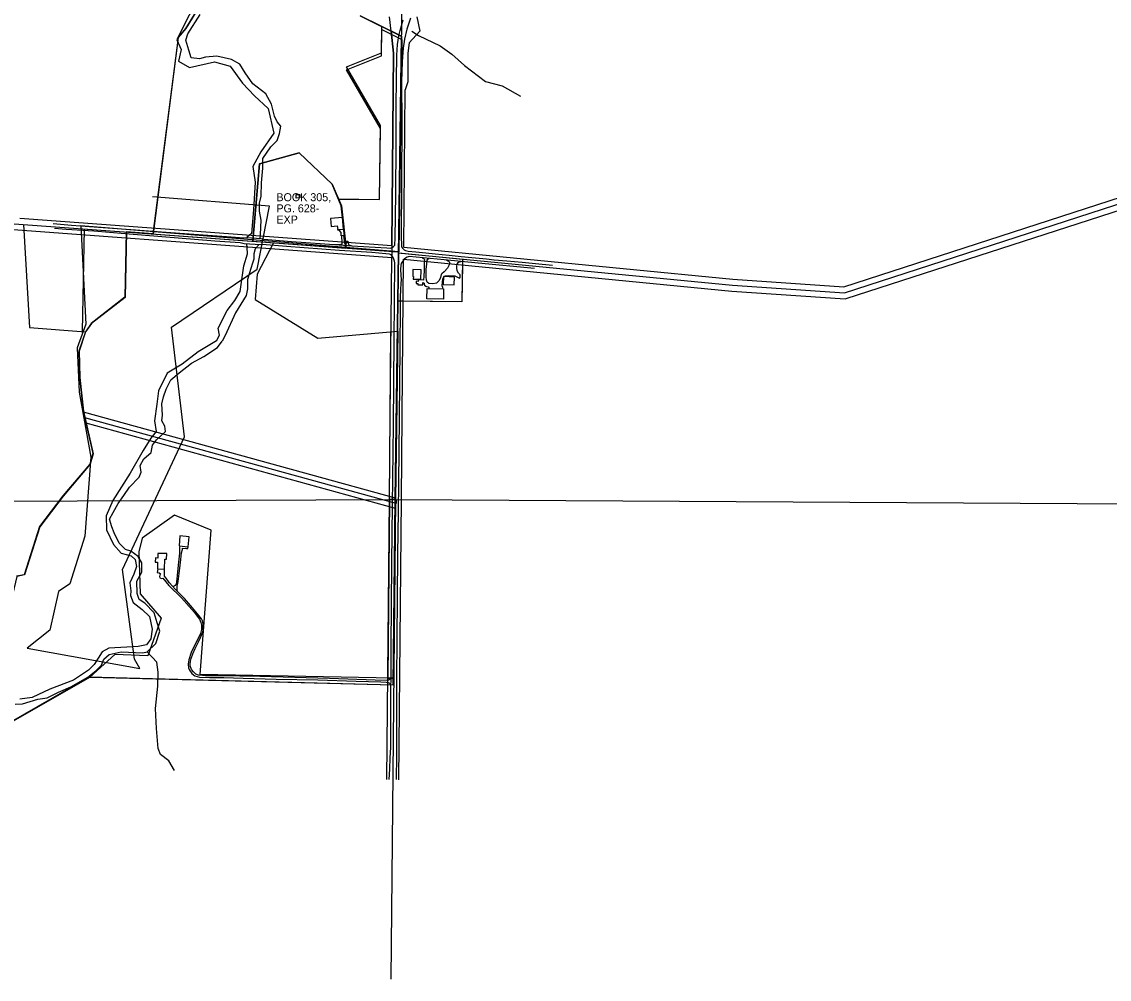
# Model space of a CAD drawing. Extents: x 171944 to 348094, y 278777 to 304794.
# Drawn here: x 175290 to 180723, y 283855 to 288639 of the extents above; entities that cross this region are included whole.
import ezdxf

# ---------------------------------------------------------------- set-up
doc = ezdxf.new("R2010")
doc.units = 0
for name, color, linetype in [('_CIVIL_CONSTRUCTION', 7, 'Continuous'), ('Default', 7, 'Continuous'), ('DR_Ditch', 7, 'Continuous'), ('DR_P_Erosion_Control', 7, 'Continuous'), ('DR_X_Ditch', 7, 'Continuous'), ('PF_P_Text_Strip_Grades_50', 7, 'Continuous'), ('PF_X_Text_Strip_Grade', 7, 'Continuous'), ('PV_P_Curb', 7, 'Continuous'), ('PV_X_Driveway', 7, 'Continuous'), ('RW_P_Const_Limits', 7, 'Continuous'), ('SH_Border', 7, 'Continuous'), ('SV_X_Toe_of_Slope', 7, 'Continuous'), ('UT_X_Electric', 7, 'Continuous')]:
    doc.layers.add(name, color=color, linetype=linetype)

msp = doc.modelspace()

# ---------------------------------------------------------------- linework, layer by layer
at = {"layer": '_CIVIL_CONSTRUCTION'}
for p, q in [((177135, 288591.8), (177127, 288663.2)), ((177264.1, 288662.8), (177278.5, 288592.3)), ((177147.2, 288481.8), (177135, 288591.8)), ((177278.5, 288592.3), (177225.9, 288533)), ((177225.9, 288533), (177219.3, 288481.1)), ((177138.6, 287521.5), (177147.2, 288481.8)), ((177219.3, 288481.1), (177218, 288338.6)), ((177218, 288338.6), (177205.6, 288298.7)), ((177198.5, 287512.3), (177205.6, 288298.7)), ((179396.6, 287314.9), (181543, 288010.2)), ((179409.6, 287256), (181561.3, 287953.1)), ((175280.8, 287657.8), (177138.6, 287521.5)), ((175224.4, 287601.8), (176532.3, 287505.8)), ((176532.3, 287505.8), (177138.1, 287461.4)), ((177130.9, 286673.3), (177138.1, 287461.4)), ((177190.9, 286672.8), (177198, 287452.1)), ((179404.1, 287254.3), (179409.6, 287256)), ((177127.1, 286252.6), (177130.9, 286673.3)), ((177187.1, 286252), (177190.9, 286672.8)), ((177113.3, 284852.7), (177127.1, 286252.6)), ((177173.3, 284852.1), (177187.1, 286252))]:
    msp.add_line(p, q, dxfattribs=at)
for points in [[(177198.5, 287512.3), (178843, 287352.1), (179396.6, 287314.9)], [(177198, 287452.1), (178838.1, 287292.3), (179404.1, 287254.3)]]:
    msp.add_lwpolyline(points, dxfattribs=at)
at = {"layer": 'Default'}
msp.add_line((177138.6, 287521.5), (177138.1, 287461.4), dxfattribs=at)
for points in [[(177138.6, 287521.5), (177138.3, 287491.5), (177173.8, 287488.9), (177188.3, 288565.8), (177134.9, 288592), (177147.2, 288481.8)], [(177127.1, 286252.2), (177134.7, 287089.8), (177168.4, 287092.8), (177157.1, 286252.3)], [(177118.3, 285360.2), (177148.3, 285359.7), (177157.1, 286252.3), (177127.1, 286252.2)]]:
    msp.add_lwpolyline(points, close=True, dxfattribs=at)
at = {"layer": 'DR_Ditch'}
for points in [[(176190.2, 288795.8), (176094.6, 288610.5), (176064.4, 288548.9), (176086.7, 288500.3), (176072.5, 288441.9)], [(176480.8, 287555.4), (176481.9, 287576.3), (176485.6, 287647.4), (176478.2, 287692.3), (176477.1, 287732.1), (176486.6, 287766.8), (176487.7, 287833.4), (176493.6, 287907.2), (176493.5, 287955.6), (176535, 288014.3), (176566, 288045.7), (176578.1, 288080.4), (176583.9, 288116.5), (176565.3, 288139.1), (176552.2, 288167.8), (176538, 288226.3), (176508.6, 288279.4), (176444.3, 288327.8), (176405.3, 288383.3), (176380, 288427), (176338.1, 288450), (176264.4, 288466.5), (176208.4, 288462.4), (176178.3, 288453.4), (176136.4, 288458.1), (176125.2, 288496.5), (176109.9, 288546.6), (176119.3, 288579.1), (176180.6, 288674.7)], [(176072.5, 288441.9), (176127.6, 288410.8), (176252.8, 288438.4), (176330.6, 288417.1), (176392.5, 288332.1), (176452.1, 288268.4), (176521.7, 288205.2), (176550, 288081.3), (176484.5, 287989.2), (176445, 287914.8), (176456.8, 287836.9), (176447.4, 287698.8), (176438.1, 287581.2), (176413.6, 287561)], [(176263.1, 287045.4), (176277.9, 287072.6), (176271.4, 287107.4), (176316.8, 287195.9), (176355.2, 287246.1), (176380.5, 287291), (176389.9, 287349.4), (176398.8, 287419), (176417.7, 287479.2), (176415.6, 287510.3), (176415.2, 287529)], [(176473.8, 287524.8), (176455.9, 287503.6), (176449.5, 287479.3), (176450.1, 287452.7), (176443, 287432), (176433.6, 287406.1), (176417.1, 287351.8), (176417.1, 287303.9), (176411.2, 287270.9), (176357.5, 287184.1), (176306.8, 287070.8), (176291.5, 287043.6)], [(175257.2, 285229.3), (175293.2, 285231.1), (175369.3, 285254.1), (175417.1, 285261.8), (175473.1, 285290.1), (175534.4, 285316.6), (175619.4, 285363.8), (175659.4, 285396.7), (175688.3, 285425), (175700.1, 285454), (175726.6, 285478.2), (175786.2, 285490.6), (175894.7, 285485.2), (175916.5, 285491.2), (175959, 285533.1), (175980.2, 285593.9), (175966.1, 285635.2), (175951.9, 285686.5), (175905.3, 285734.3), (175876.4, 285752), (175867, 285781.6), (175865.2, 285843.5), (175889.4, 285889.6), (175890, 285936.2), (175871.7, 285966.9), (175834.5, 285993.5), (175807.5, 286002.3), (175776.1, 286034), (175752.2, 286085.6), (175740.1, 286115.6), (175728.6, 286153.8), (175746.5, 286187.8), (175771.8, 286232.4), (175799.4, 286272.8), (175828.4, 286314.3), (175875.6, 286363.2), (175886.7, 286388.5), (175880.6, 286421.6), (175900.5, 286455), (175936.9, 286487), (175942.6, 286523.1), (175962.5, 286549.4), (175990.2, 286575.4), (176008.4, 286591.6), (176005.3, 286618.9), (175989.2, 286644.5), (175992.5, 286673.9), (175989.5, 286730.2), (175998.6, 286764.3), (176012.1, 286802.7), (176034, 286849.6), (176075.8, 286884), (176137.7, 286932.9), (176199.1, 286966.6), (176268.1, 287011.4), (176291.5, 287043.6)], [(176263.1, 287045.4), (176170.5, 286989.3), (176092.1, 286927.3), (176016.7, 286882.9), (175972.4, 286795.1), (175964.1, 286727.9), (175953.8, 286645.3), (175962, 286591.6), (175935.2, 286558.5), (175896, 286496.5), (175830.7, 286384.2), (175745, 286247.8), (175711, 286170.4), (175714, 286101.2), (175748.1, 286027.8), (175787.3, 285983.4), (175836.9, 285970), (175856.2, 285953.1), (175862.3, 285917), (175850.5, 285878.6), (175829.8, 285835.5), (175834.6, 285796), (175833.4, 285772.4), (175846.4, 285737), (175891.8, 285702.1), (175927.8, 285667.9), (175941.9, 285604.8), (175934.8, 285555.8), (175912.4, 285525.7), (175871.7, 285517.4), (175814.5, 285515), (175784.4, 285512.7), (175724.9, 285509.7), (175691.2, 285491.4), (175652.3, 285428.3), (175624, 285399.5), (175547.6, 285349.9), (175429.9, 285304.5), (175341.2, 285263.1), (175280.3, 285254.9)]]:
    msp.add_lwpolyline(points, dxfattribs=at)
at = {"layer": 'DR_P_Erosion_Control'}
for p, q in [((177157.2, 286259.3), (175598.5, 286688.6)), ((177156.7, 286207.6), (175611.9, 286633.1))]:
    msp.add_line(p, q, dxfattribs=at)
at = {"layer": 'DR_X_Ditch'}
for points in [[(177238.7, 288592), (177272.3, 288570.3), (177380.1, 288518.9), (177438.3, 288476.1), (177501.5, 288420.8), (177606.9, 288339.5), (177690.4, 288318.4), (177781.3, 288267.2)], [(176052.9, 284898.2), (176024, 284947), (175982.5, 284977.7), (175971.6, 285008.5), (175962.6, 285107.9), (175957.2, 285207.3), (175969.8, 285319.4), (175971.6, 285389.9), (175965.3, 285438.6), (175916.5, 285491.2)]]:
    msp.add_lwpolyline(points, dxfattribs=at)
at = {"layer": 'PF_P_Text_Strip_Grades_50'}
for points in [[(176209.2, 288769.2), (176108.8, 288605.8), (176072, 288560.6), (175946.6, 287579), (175812.1, 287588.9), (175805.2, 287262), (175636.7, 287132.1), (175607.7, 287090.1), (175575.6, 286993.2), (175578.4, 286862.5), (175596.4, 286693.9), (175645.4, 286481), (175630.7, 286428.9), (175494.7, 286269.7), (175378.5, 286116.7), (175302.3, 285875.9), (175263.9, 285868.2)], [(177155.3, 286252.2), (177187.8, 288566.1), (176980.6, 288668)], [(177173.8, 287488.9), (176910.4, 287508.2), (176886.6, 287719.5), (176872.2, 287753.2), (177077.3, 287750), (177082.1, 288105.3), (176912, 288398.5), (177087.1, 288467.8), (177088.9, 288599.7), (177188.2, 288550.4), (177173.8, 287488.9)], [(177155.3, 286252.2), (177172.7, 287488.4), (176909.3, 287507.9), (176885.6, 287719.1), (176840, 287826.6), (176675.3, 287984.3), (176477.5, 287929.4), (176443.6, 287542.3), (176909.3, 287507.9)], [(177173.8, 287488.9), (175585.2, 287618.5), (175610.2, 287128.1), (175567.2, 287008.9), (175575.8, 286788.7), (175635, 286464), (175605.1, 286069.2), (175529.7, 285829.9), (175473.6, 285791.6), (175429.7, 285599.9), (175316.9, 285509.5), (175880.1, 285408.4), (175853.3, 285453.9), (175828.7, 285641), (175793.1, 285902.6), (176102.1, 286565.4), (176037.4, 287112.7), (176466.3, 287402), (176527.5, 287716.9), (175943.4, 287764.5)], [(177173.8, 287488.9), (175585.2, 287618.5), (175610.2, 287128.1), (175567.2, 287008.9), (175575.8, 286788.7), (175635, 286464), (175605.1, 286069.2), (175529.7, 285829.9), (175473.6, 285791.6), (175429.7, 285599.9), (175316.9, 285509.5), (175880.1, 285408.4), (175853.3, 285453.9), (175828.7, 285641), (175793.1, 285902.6), (176102.1, 286565.4), (176037.4, 287112.7), (176466.3, 287402), (176527.5, 287716.9), (175943.4, 287764.5)], [(177157.1, 286252.3), (177170.5, 287243.6), (177173.7, 287485.1), (177491.6, 287453), (177491.3, 287424.1), (177488.8, 287239.3), (177196.7, 287243.3), (177170.5, 287243.6)], [(177159.8, 286251.6), (177159.7, 286232.7), (175605.5, 286660.8), (175598, 286693.2), (175580.1, 286861.3)], [(175115.7, 285073.7), (175626.9, 285365.7), (177145.7, 285325.6), (177155.3, 286252.2)]]:
    msp.add_lwpolyline(points, dxfattribs=at)
at = {"layer": 'PF_X_Text_Strip_Grade'}
for p, q in [((176980.6, 288668), (177188.3, 288565.8)), ((175600.8, 287604.3), (175591.1, 287090.9))]:
    msp.add_line(p, q, dxfattribs=at)
for points in [[(175947, 287578.6), (176072.4, 288560.2), (176109.2, 288605.4), (176209.6, 288768.8), (176200, 288859.9), (176254.9, 289020.7), (176333, 289127.4), (176498.7, 289254.3), (176610.8, 289298), (176648, 289429.6), (176701.7, 289556.9), (176779.7, 289767.2), (176722, 289836.7), (176723.8, 289912.1), (176737.4, 289958.6), (176723.2, 290042.2), (176664.9, 290144.8), (176734.7, 290227.2), (176779.1, 290304.8), (176742.5, 290399.8), (176794, 290571.3), (176771.6, 290709.4), (176767.2, 290821.3)], [(176443.6, 287542.3), (176477.5, 287929.4), (176675.3, 287984.3), (176840, 287826.6), (176886.6, 287719.5), (176910.4, 287508.2)], [(175298.7, 287626.4), (175328.5, 287111.2), (175609.1, 287089.5)], [(175812.7, 287588.7), (175806.6, 287261.4), (175638.1, 287131.5), (175609.1, 287089.5), (175577.1, 286992.6), (175579.9, 286861.9), (175598, 286693.2), (175647.1, 286480.4), (175632.4, 286428.2), (175496.4, 286269), (175380.4, 286115.9), (175304.3, 285875.1), (175265.9, 285867.4), (175221.5, 285684.8), (174927.1, 285439.6), (174550.6, 284781), (175118.1, 285072.9), (175629.1, 285365.1), (177148, 285325.7)], [(176547.2, 287534.8), (176466.4, 287378), (176455.9, 287250.8), (176769.9, 287057.5), (177168.4, 287092.8)], [(177491.6, 287453.6), (177488.8, 287239.1), (177170.5, 287243.4)], [(177148.3, 285359.7), (176180.9, 285377.7), (176236.4, 286099.1), (176053.1, 286174.4), (175891.7, 286058.5), (175874.6, 285990.9), (175880.7, 285781), (175986.7, 285659.8), (175920.5, 285471.5), (175755.3, 285477.3), (175629.1, 285365.1)]]:
    msp.add_lwpolyline(points, dxfattribs=at)
at = {"layer": 'PV_P_Curb'}
for p, q in [((177087.2, 288483.1), (177089, 288614.7)), ((176912.1, 288413.8), (177087.2, 288483.1)), ((177082.3, 288120.5), (176912.1, 288413.8)), ((177077.3, 287750), (177082.3, 288120.5)), ((176871.9, 287753.3), (177077.3, 287750))]:
    msp.add_line(p, q, dxfattribs=at)
msp.add_lwpolyline([(176871.9, 287753.3), (177077.3, 287750), (177082.3, 288120.5)], dxfattribs=at)
at = {"layer": 'PV_X_Driveway'}
for points in [[(176854.2, 287525.9), (176867.7, 287526.3), (176884, 287526.8), (176888.3, 287526.6), (176890.1, 287528.6), (176891.1, 287534.7), (176890.6, 287545.1), (176889.6, 287558), (176888.8, 287570), (176886, 287570), (176885.4, 287585.3), (176875.8, 287598.2), (176869.3, 287597.2), (176868.4, 287600.1)], [(176897.9, 287603.2), (176900.9, 287570.5), (176888.8, 287570)], [(176897.8, 287570.4), (176900.4, 287545.5), (176901, 287537.5), (176902.8, 287531.9), (176906.2, 287526.7), (176909.3, 287523), (176911.3, 287525.9), (176912.8, 287533.2), (176912.5, 287543.1), (176919.3, 287542.8), (176920.7, 287539.6), (176920.1, 287533.2), (176922.2, 287527.5), (176924.6, 287524.1), (176938.8, 287520.1)], [(177290.6, 287459.1), (177297, 287455.8), (177301.8, 287450.2), (177300.6, 287436.9), (177300.4, 287395.6), (177299.1, 287367.7), (177297.4, 287348.5), (177270.4, 287349.2), (177270.1, 287341.2), (177261.1, 287342.1), (177260.6, 287331.8), (177269.4, 287331.8), (177269.1, 287324.2), (177293.6, 287324.2), (177294.2, 287331.1), (177294.3, 287335.4), (177297.8, 287334.6), (177299.8, 287332.8), (177300.7, 287328.1), (177302.9, 287323.5), (177308.9, 287318.2), (177312.7, 287316.5), (177319.7, 287314.3), (177323.7, 287313.3), (177323.5, 287305.9)], [(177412.7, 287447.9), (177421.4, 287443.4), (177426.8, 287436.9), (177425.8, 287424.7), (177417.3, 287407.6), (177399.6, 287390.1), (177388.8, 287380), (177385, 287376), (177381.9, 287361.5), (177374.8, 287345.7), (177361.3, 287333), (177343.4, 287328.6), (177324.3, 287330.7), (177315.5, 287338), (177312, 287348.2), (177310.1, 287364.8), (177311.2, 287402), (177314.1, 287427.4), (177316, 287446.9), (177319.5, 287452.1), (177324.7, 287456)], [(177435.1, 287369.5), (177453.8, 287368.7), (177466.3, 287363.5), (177476.7, 287357.9), (177480.1, 287361.8), (177479.6, 287374.7), (177472.6, 287383.3), (177465.7, 287393.6), (177463.6, 287409), (177463.2, 287418), (177464.7, 287428.1), (177470.5, 287436.5), (177474.6, 287439.6), (177485.9, 287440.8)], [(177394.9, 287303.9), (177394.4, 287310.6), (177391, 287319.3), (177392.5, 287339.6), (177394.1, 287353.5), (177397, 287361.9)], [(177400.6, 287366.2), (177405.4, 287369.7), (177422, 287371.4), (177435.1, 287369.5), (177453.8, 287368.7)], [(176080.1, 286020.1), (176078.5, 286010.3), (176077.6, 285984.5), (176073.1, 285938.2), (176067, 285873.6), (176065.4, 285854), (176061.1, 285829.6), (176055.9, 285822.4), (176046.1, 285816.3)], [(176067.7, 285793.1), (176065.9, 285801.7), (176066.8, 285819), (176069.6, 285832.3), (176073.7, 285855.7), (176079.7, 285909.7), (176085.1, 285951.7), (176088.4, 285986), (176092.4, 286001.6), (176093.7, 286008.8), (176113.6, 286006.8), (176120.1, 286006.6), (176121.8, 286016.3)], [(175968.9, 285905.1), (175967, 285887.2), (175976.6, 285886), (175982.5, 285880), (175980.1, 285874.8), (175978.3, 285867), (175980.1, 285860.4), (175987.8, 285857.4), (175994.7, 285858.8), (176025.1, 285823.2), (176087.3, 285760.4), (176126, 285717.2), (176152.8, 285687.9), (176166.7, 285669.8), (176177.4, 285653.8), (176184.6, 285637.8), (176188.6, 285623.5), (176187.7, 285602.3), (176182.5, 285583.1), (176172.6, 285561.3), (176154.9, 285526.4), (176136.6, 285487.7), (176125.3, 285451), (176121.4, 285429.7), (176122.4, 285411.5), (176127.8, 285399.8), (176139.1, 285382.4), (176154.7, 285371.8), (176178.4, 285364.3), (176228.1, 285363), (176298.8, 285362.4), (176395.7, 285360.1), (176561.1, 285354.7), (176768.9, 285350.4), (176961.5, 285344.5), (177083.2, 285340.4), (177110.6, 285339.5), (177120.3, 285337.2), (177130, 285332.1), (177134.4, 285324)], [(177134.8, 285359.4), (177130, 285354.4), (177122.4, 285349.4), (177113.5, 285348.2), (177055.5, 285349.8), (176827.7, 285357.1), (176479.2, 285367.1), (176277.5, 285371.3), (176208.4, 285371.4), (176192.6, 285372.5), (176172.6, 285375.2), (176159.9, 285380.1), (176147.4, 285390.8), (176138.3, 285402.1), (176131.8, 285421.3), (176132, 285429.9), (176133.5, 285444.3), (176136.6, 285457.6), (176144.7, 285481.1), (176155.9, 285508.3), (176172.4, 285541.5), (176182.9, 285562.3), (176192.2, 285585.3), (176195.4, 285596.9), (176196.4, 285608.1), (176197, 285616.7), (176196.2, 285628.5), (176192.1, 285645.3), (176187.1, 285656.3), (176168.4, 285681.5), (176143.6, 285711.6), (176102.5, 285756.8), (176058.5, 285802.4), (176027.1, 285838.1), (176010.5, 285858.7), (176003.6, 285869.5), (176003.6, 285874.1), (176002.9, 285903.6)]]:
    msp.add_lwpolyline(points, dxfattribs=at)
at = {"layer": 'RW_P_Const_Limits'}
for p, q in [((177157.1, 286252.3), (177192.7, 288892.2)), ((174537, 286240.3), (177157.1, 286252.3)), ((177157.1, 286252.3), (182447, 286220.4))]:
    msp.add_line(p, q, dxfattribs=at)
at = {"layer": 'SH_Border'}
for p, q in [((175252.6, 287629.8), (177173.8, 287488.9)), ((175252.6, 287629.8), (177168.3, 287489.3)), ((177157.1, 286252.3), (177133.4, 283855.3))]:
    msp.add_line(p, q, dxfattribs=at)
for points in [[(179400.4, 287284.6), (181552.2, 287981.7), (182472.1, 288269.2)], [(177168.3, 287485.1), (178840.6, 287322.2), (179400.4, 287284.6)]]:
    msp.add_lwpolyline(points, dxfattribs=at)
at = {"layer": 'SV_X_Toe_of_Slope'}
for points in [[(176679.8, 287758.6), (176661, 287757.6), (176660.3, 287775), (176679.6, 287776), (176679.8, 287759.3)], [(176868.4, 287600.1), (176897.9, 287603.2), (176891.9, 287661), (176832.4, 287655.2), (176836.1, 287615.7), (176866.5, 287619.2)], [(177243, 287366.6), (177246.6, 287366.4), (177246.2, 287353.5), (177284.6, 287352.2), (177286.1, 287399.8), (177244.1, 287401.1)], [(177396.2, 287326), (177450.8, 287324.3), (177452.4, 287363.1), (177397.8, 287365.8)], [(177315.3, 287306), (177397.8, 287303.7), (177396.7, 287253.5), (177314.1, 287254.1)], [(176075.7, 286020.3), (176121.8, 286016.3), (176125.9, 286065.9), (176080.4, 286070.2)], [(175967.5, 285905.7), (176002.9, 285903.6), (176005.2, 285953.2), (176013.3, 285953.2), (176014, 285982.2), (175970.2, 285982.9), (175969.2, 285959.6), (175957.4, 285960.3), (175957, 285938.7), (175968.5, 285938.7)]]:
    msp.add_lwpolyline(points, close=True, dxfattribs=at)
at = {"layer": 'UT_X_Electric'}
for points in [[(175446.9, 287630.2), (175537.8, 287622.4), (175673.2, 287613.1), (175858.3, 287599.6), (175988.5, 287589.8), (176150.3, 287576.9), (176335.7, 287564.8), (176398.9, 287560), (176413.6, 287561), (176486.7, 287555.2), (176498.5, 287551.9), (176637.2, 287540.4), (176876, 287524.3), (176938.8, 287520.1), (177114.4, 287508.5), (177130.4, 287507.9), (177140.6, 287511.3), (177147, 287515.7), (177153.1, 287522.8), (177154.3, 287527.4), (177155, 287553.6), (177157.4, 287669), (177158.4, 287776.6), (177160.5, 288025.1), (177160.9, 288216.9), (177162.5, 288349.7), (177163.8, 288471), (177167.5, 288525.3), (177174.2, 288569.1), (177179.9, 288595.3), (177195.7, 288647.5)], [(177232.6, 288656.2), (177213.1, 288602.2), (177202.7, 288552.1), (177195.6, 288506), (177190.1, 288439.5), (177187.2, 288337.8), (177188.7, 288132.3), (177185.2, 287558.4), (177186.5, 287528.5), (177187.9, 287514.2), (177192.4, 287507.8), (177200, 287498.8), (177207.5, 287495.9), (177220.1, 287493.4), (177259.5, 287489), (177309.3, 287483.7), (177354.6, 287478.9), (177424.7, 287472.3), (177486.1, 287466.6), (177538.2, 287461.6), (177612.7, 287453.9), (177650.1, 287450.1), (177713.1, 287444.6), (177789.7, 287437), (177856.3, 287430.5), (177941, 287422.6)], [(177126, 284852.9), (177128.5, 284905.1), (177130.5, 284962.1), (177134.1, 285013.6), (177134.4, 285075.3), (177134.3, 285160), (177134.3, 285305.4), (177135.1, 285366.7), (177135.7, 285514.9), (177138.9, 285936.4), (177143, 286223.6), (177146.9, 286623.1), (177151.3, 287047.5), (177153.7, 287433.7), (177152.9, 287442.2), (177147.3, 287457.2), (177142.5, 287465.5), (177134.8, 287474), (177126.5, 287477.2), (177109.6, 287479.3), (177039, 287485.3), (176877.2, 287496.6), (176613.4, 287516.1), (176490.4, 287525.9), (176481.9, 287524), (176401.2, 287530), (176381.2, 287533.7), (176253.8, 287542.9), (175806.8, 287578.9), (175649.8, 287592.4), (175511.6, 287601.4), (175454, 287605.1)], [(177852.4, 287405.8), (177571, 287432.8), (177399.8, 287449.3), (177226.3, 287465.2), (177215, 287462.8), (177202.3, 287454.8), (177191.5, 287441.6), (177186.3, 287431.3), (177183.9, 287422), (177183, 287401.5), (177183.9, 287372.8), (177185.3, 287351.2), (177184.4, 287329.7), (177182.7, 287302.5), (177180.6, 287261), (177180.4, 287208.4), (177179, 287012.2), (177175.1, 286657.4), (177172.3, 286335.4), (177170.3, 286192.9), (177168, 285977.6), (177165.5, 285762.5), (177161.8, 285350), (177161.9, 285305.3), (177161.4, 285264.5), (177161.5, 285169.3), (177161.8, 284973.1), (177160.6, 284852.9)]]:
    msp.add_lwpolyline(points, dxfattribs=at)

# ---------------------------------------------------------------- texts
at = {"layer": 'PF_P_Text_Strip_Grades_50'}
for s, p in [('BOOK 305,', (176562.2, 287742.2)), ('PG. 628-', (176562.2, 287686.5)), ('EXP', (176562.2, 287630.8))]:
    msp.add_text(s, height=40, dxfattribs=at).set_placement(p)

doc.saveas('drawing.dxf')
